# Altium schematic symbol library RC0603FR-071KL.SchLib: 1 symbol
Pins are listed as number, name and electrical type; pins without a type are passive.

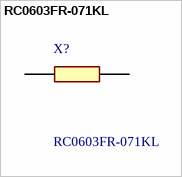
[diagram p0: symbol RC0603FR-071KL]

## RC0603FR-071KL
designator X?
Res Thick Film 0603 1K Ohm 1% 0.1W(1/10W) +/-100ppm/C Epoxy Pad SMD T/R; Manufacturer_Name: Yageo Group; Geometry.Height: 0.55mm
footprint RESC1608X55N
pins: 1, 2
